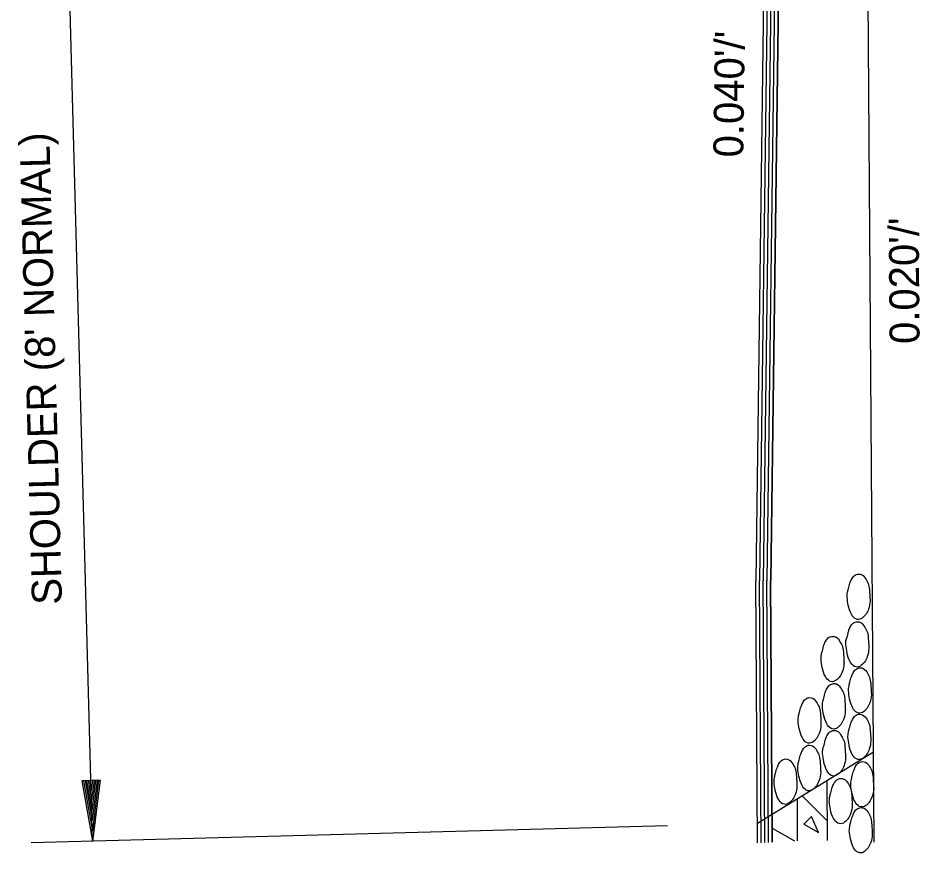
# Model space of a CAD drawing. Extents: x 1926836 to 1933254, y 596317 to 604524.
# Drawn here: x 1932876.6 to 1933059.5, y 600103.1 to 600272.6 of the extents above; entities that cross this region are included whole.
import ezdxf

# ---------------------------------------------------------------- set-up
doc = ezdxf.new("R2010")
doc.units = 0
doc.layers.add('Default', color=7, linetype='Continuous')

msp = doc.modelspace()

# ---------------------------------------------------------------- linework, layer by layer
at = {"layer": 'Default'}
for p, q in [((1933050.22, 600105.35), (1933047.48, 600498.79)), ((1932891.73, 600105.54), (1932882.86, 600435.95)), ((1933028.17, 600306.1), (1933026.23, 600158.37)), ((1933028.91, 600306.12), (1933026.96, 600158.39)), ((1933029.64, 600306.09), (1933027.7, 600158.36)), ((1933030.38, 600306.11), (1933028.44, 600158.38)), ((1933031.12, 600306.08), (1933029.18, 600158.35)), ((1933031.22, 600306.08), (1933029.28, 600158.45)), ((1933026.6, 600105.19), (1933026.23, 600158.37)), ((1933027.33, 600105.21), (1933026.96, 600158.39)), ((1933028.07, 600105.26), (1933027.7, 600158.41)), ((1933028.81, 600105.3), (1933028.44, 600158.43)), ((1933029.54, 600105.35), (1933029.18, 600158.4)), ((1933029.64, 600105.35), (1933029.28, 600158.45)), ((1933050.1, 600123.62), (1933026.57, 600109.16)), ((1932893.27, 600117.91), (1932889.56, 600117.81)), ((1932889.56, 600117.81), (1932891.73, 600105.54)), ((1932889.88, 600117.82), (1932891.68, 600107.6)), ((1932890.2, 600117.83), (1932891.62, 600109.72)), ((1932890.49, 600117.83), (1932891.57, 600111.78)), ((1932890.81, 600117.84), (1932891.51, 600113.85)), ((1932891.13, 600117.85), (1932891.45, 600115.92)), ((1932891.7, 600117.87), (1932891.45, 600115.92)), ((1932892.02, 600117.88), (1932891.51, 600113.85)), ((1932892.34, 600117.88), (1932891.57, 600111.78)), ((1932892.63, 600117.89), (1932891.62, 600109.72)), ((1932892.95, 600117.9), (1932891.68, 600107.6)), ((1932893.27, 600117.91), (1932891.73, 600105.54)), ((1933040.75, 600105.65), (1933040.67, 600117.82)), ((1933040.73, 600109.64), (1933035.64, 600114.73)), ((1933034.71, 600105.61), (1933034.65, 600114.12)), ((1933008.33, 600108.67), (1932879.24, 600105.2)), ((1933034.12, 600105.57), (1933029.59, 600108.11))]:
    msp.add_line(p, q, dxfattribs=at)
msp.add_lwpolyline([(1933038.93, 600107.33), (1933037.51, 600110.54), (1933035.98, 600109.02), (1933038.93, 600107.33)], dxfattribs=at)
for points in [[(1933044.74, 600155.05), (1933044.98, 600153.43), (1933045.62, 600151.58), (1933046.48, 600150.66), (1933047.03, 600150.53), (1933048, 600151), (1933048.53, 600151.55), (1933049.09, 600152.65), (1933049.39, 600154.24), (1933049.37, 600155.02), (1933049.29, 600156.25), (1933049.1, 600157.58), (1933048.58, 600158.64), (1933047.72, 600159.61), (1933047.08, 600159.74), (1933046.2, 600159.42), (1933045.63, 600158.66), (1933045.3, 600157.92), (1933045.04, 600156.83), (1933044.81, 600156.08), (1933044.74, 600155.05)], [(1933044.49, 600145.39), (1933044.73, 600143.77), (1933045.37, 600141.92), (1933046.23, 600141.01), (1933046.78, 600140.88), (1933047.75, 600141.34), (1933048.28, 600141.9), (1933048.84, 600143), (1933049.14, 600144.58), (1933049.12, 600145.37), (1933049.04, 600146.6), (1933048.85, 600147.92), (1933048.33, 600148.99), (1933047.47, 600149.95), (1933046.83, 600150.08), (1933045.95, 600149.76), (1933045.38, 600149.01), (1933045.06, 600148.26), (1933044.79, 600147.17), (1933044.56, 600146.43), (1933044.49, 600145.39)], [(1933039.46, 600142.42), (1933039.7, 600140.8), (1933040.34, 600138.95), (1933041.2, 600138.03), (1933041.75, 600137.9), (1933042.72, 600138.37), (1933043.25, 600138.93), (1933043.81, 600140.02), (1933044.11, 600141.61), (1933044.09, 600142.39), (1933044.01, 600143.62), (1933043.82, 600144.95), (1933043.3, 600146.02), (1933042.44, 600146.98), (1933041.8, 600147.11), (1933040.92, 600146.79), (1933040.35, 600146.04), (1933040.02, 600145.29), (1933039.76, 600144.2), (1933039.53, 600143.45), (1933039.46, 600142.42)], [(1933045.01, 600136.03), (1933045.25, 600134.41), (1933045.89, 600132.56), (1933046.75, 600131.64), (1933047.34, 600131.51), (1933048.31, 600131.98), (1933048.79, 600132.54), (1933049.35, 600133.63), (1933049.66, 600135.22), (1933049.63, 600136), (1933049.55, 600137.23), (1933049.37, 600138.56), (1933048.9, 600139.63), (1933047.99, 600140.59), (1933047.39, 600140.72), (1933046.51, 600140.4), (1933045.94, 600139.65), (1933045.62, 600138.9), (1933045.3, 600137.81), (1933045.13, 600137.07), (1933045.01, 600136.03)], [(1933039.73, 600132.84), (1933039.97, 600131.23), (1933040.62, 600129.37), (1933041.48, 600128.41), (1933042.02, 600128.28), (1933042.99, 600128.75), (1933043.52, 600129.3), (1933044.08, 600130.4), (1933044.38, 600131.98), (1933044.36, 600132.82), (1933044.28, 600134.05), (1933044.1, 600135.37), (1933043.58, 600136.39), (1933042.71, 600137.4), (1933042.07, 600137.53), (1933041.19, 600137.21), (1933040.62, 600136.46), (1933040.3, 600135.71), (1933040.03, 600134.57), (1933039.81, 600133.88), (1933039.73, 600132.84)], [(1933034.79, 600129.99), (1933035.03, 600128.38), (1933035.67, 600126.52), (1933036.53, 600125.56), (1933037.13, 600125.43), (1933038.1, 600125.9), (1933038.58, 600126.45), (1933039.14, 600127.55), (1933039.44, 600129.14), (1933039.42, 600129.97), (1933039.34, 600131.2), (1933039.15, 600132.52), (1933038.68, 600133.54), (1933037.77, 600134.55), (1933037.17, 600134.69), (1933036.3, 600134.37), (1933035.73, 600133.61), (1933035.4, 600132.87), (1933035.09, 600131.73), (1933034.91, 600131.03), (1933034.79, 600129.99)], [(1933044.9, 600126.62), (1933045.14, 600125.01), (1933045.78, 600123.15), (1933046.64, 600122.24), (1933047.23, 600122.11), (1933048.21, 600122.58), (1933048.68, 600123.13), (1933049.24, 600124.23), (1933049.55, 600125.81), (1933049.53, 600126.6), (1933049.44, 600127.83), (1933049.26, 600129.15), (1933048.79, 600130.22), (1933047.88, 600131.18), (1933047.28, 600131.31), (1933046.4, 600131), (1933045.83, 600130.24), (1933045.51, 600129.49), (1933045.19, 600128.4), (1933045.02, 600127.66), (1933044.9, 600126.62)], [(1933039.77, 600123.33), (1933040.01, 600121.71), (1933040.65, 600119.86), (1933041.51, 600118.89), (1933042.06, 600118.76), (1933043.03, 600119.23), (1933043.56, 600119.79), (1933044.12, 600120.88), (1933044.42, 600122.47), (1933044.4, 600123.3), (1933044.31, 600124.53), (1933044.13, 600125.86), (1933043.61, 600126.88), (1933042.75, 600127.89), (1933042.1, 600128.02), (1933041.23, 600127.7), (1933040.66, 600126.94), (1933040.33, 600126.2), (1933040.07, 600125.06), (1933039.84, 600124.36), (1933039.77, 600123.33)], [(1933034.73, 600120.33), (1933034.97, 600118.71), (1933035.61, 600116.86), (1933036.47, 600115.9), (1933037.07, 600115.76), (1933038.04, 600116.23), (1933038.52, 600116.79), (1933039.08, 600117.89), (1933039.38, 600119.47), (1933039.36, 600120.31), (1933039.28, 600121.53), (1933039.09, 600122.86), (1933038.62, 600123.88), (1933037.71, 600124.89), (1933037.11, 600125.02), (1933036.24, 600124.7), (1933035.67, 600123.95), (1933035.34, 600123.2), (1933035.03, 600122.06), (1933034.85, 600121.37), (1933034.73, 600120.33)], [(1933029.92, 600117.52), (1933030.16, 600115.91), (1933030.8, 600114.05), (1933031.66, 600113.14), (1933032.25, 600113.01), (1933033.22, 600113.48), (1933033.7, 600114.03), (1933034.26, 600115.13), (1933034.56, 600116.71), (1933034.54, 600117.5), (1933034.46, 600118.73), (1933034.28, 600120.05), (1933033.81, 600121.12), (1933032.89, 600122.08), (1933032.3, 600122.22), (1933031.42, 600121.9), (1933030.85, 600121.14), (1933030.53, 600120.4), (1933030.21, 600119.3), (1933030.03, 600118.56), (1933029.92, 600117.52)], [(1933045.48, 600116.99), (1933045.72, 600115.37), (1933046.36, 600113.52), (1933047.22, 600112.61), (1933047.81, 600112.48), (1933048.78, 600112.94), (1933049.26, 600113.5), (1933049.82, 600114.6), (1933050.13, 600116.18), (1933050.1, 600116.97), (1933050.02, 600118.2), (1933049.84, 600119.52), (1933049.37, 600120.59), (1933048.46, 600121.55), (1933047.86, 600121.68), (1933046.98, 600121.36), (1933046.41, 600120.61), (1933046.09, 600119.86), (1933045.77, 600118.77), (1933045.6, 600118.03), (1933045.48, 600116.99)], [(1933041.12, 600113.59), (1933041.36, 600111.97), (1933042, 600110.12), (1933042.86, 600109.21), (1933043.46, 600109.08), (1933044.43, 600109.55), (1933044.91, 600110.1), (1933045.47, 600111.2), (1933045.77, 600112.78), (1933045.75, 600113.57), (1933045.67, 600114.8), (1933045.48, 600116.12), (1933045.01, 600117.19), (1933044.1, 600118.15), (1933043.51, 600118.28), (1933042.63, 600117.96), (1933042.06, 600117.21), (1933041.73, 600116.46), (1933041.42, 600115.37), (1933041.24, 600114.63), (1933041.12, 600113.59)], [(1933045.19, 600107.67), (1933045.43, 600106.05), (1933046.07, 600104.2), (1933046.94, 600103.29), (1933047.53, 600103.16), (1933048.5, 600103.63), (1933048.98, 600104.18), (1933049.54, 600105.28), (1933049.84, 600106.86), (1933049.82, 600107.65), (1933049.74, 600108.88), (1933049.56, 600110.2), (1933049.08, 600111.27), (1933048.17, 600112.23), (1933047.58, 600112.36), (1933046.7, 600112.04), (1933046.13, 600111.29), (1933045.81, 600110.54), (1933045.49, 600109.45), (1933045.31, 600108.71), (1933045.19, 600107.67)]]:
    msp.add_spline(points, degree=3, dxfattribs=at)

# ---------------------------------------------------------------- texts
for s, rotation, p in [("0.040'/'", 89.2471, (1933023.67, 600244.28)), ("SHOULDER (8' NORMAL)", 91.5377, (1932885.52, 600153.6)), ("0.020'/'", 90.3914, (1933059.44, 600206.47))]:
    msp.add_text(s, height=6.075, rotation=rotation, dxfattribs=at).set_placement(p)

doc.saveas('drawing.dxf')
